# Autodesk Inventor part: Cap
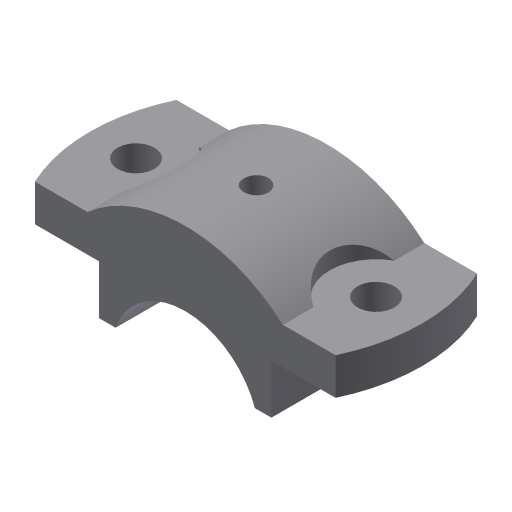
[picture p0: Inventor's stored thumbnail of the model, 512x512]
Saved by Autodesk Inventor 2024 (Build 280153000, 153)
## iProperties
Shininess: 77.0
Angle Display Precision: 2
Document Length Units: 11269
Document Angle Units: 11279
Document Time Units: 11290
Document Mass Units: 11283
Document Length Units Precision: 3
Document Angle Units Precision: 2
Created: 2002-02
Part Number: Cap
Document SubType Name: Modeling
Designer: ***
Density: 1 g/cm^3
Material: Generic
Appearance: Default
Density: 0.0
Volumn: 0.0
Area: 0.0
PropertySet Name: Model Information
Control State: 0
Master: False
Checked Out: False
Author: ***
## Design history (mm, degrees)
sketch "Sketch2"
  geometry: L1 (22.656, 22.99)-(28.029, 22.99); L2 (28.029, 22.99)-(28.029, 38.99); L3 (28.029, 38.99)-(54.029, 38.99); L4 (54.029, 38.99)-(54.029, 50.99); L5 (54.029, 50.99)-(31.778, 50.99); L6 (-22.599, 22.99)-(-27.971, 22.99); L7 (-27.971, 22.99)-(-27.971, 38.99); L8 (-27.971, 38.99)-(-53.971, 38.99); L9 (-53.971, 38.99)-(-53.971, 50.99); L10 (-53.971, 50.99)-(-31.72, 50.99); A1 r 24 centre (0.029, 14.99) between (22.656, 22.99) and (-22.599, 22.99); A2 r 48 centre (0.029, 14.99) between (31.778, 50.99) and (-31.72, 50.99)
  constraints: 20 end point, 5 equal length, 4 parallel, 4 perpendicular, 4 point on circle, 2 centre point, 1 coincident, 1 horizontal, 1 point on line
  dimensions: "d0" = 24 radius of A1; "d1" = 8 distance from line of L1 A1.centre; "d2" = 12 distance of L8.end L9.end; "d3" = 16 distance of L6.end L7.end; "d4" = 48 radius of A2; "d5" = 108 distance between parallel lines of L9 L4; "d6" = 56 distance between parallel lines of L7 L2
extrude "Extrusion1" new body sketch "Sketch2" stored distance "d7" = 46; taper "d8" = 0 deg
sketch "Sketch3"
  geometry: L1 (17.108, 0)-(40.349, 0); L2 (40.349, 0)-(40.349, -46); L3 (40.349, -46)-(17.108, -46); L4 (0, -46)-(22.251, -46) reference; L5 (22.251, 0)-(0, 0) reference; L6 (22.251, 0)-(22.251, -46) reference; A1 r 54 centre (-31.749, -23) between (17.108, -46) and (17.108, 0)
  constraints: 6 end point, 2 collinear, 2 point on circle, 1 centre point, 1 horizontal, 1 parallel, 1 perpendicular, 1 vertical alignment
  dimensions: "d9" = 54 radius of A1; "d10" = 54 distance from line of L6 A1.centre
extrude "Extrusion2" cut sketch "Sketch3" extent not by distance; stored distance "d11" = 46; taper "d12" = 0 deg
sketch "Sketch4"
  geometry: L1 (17.108, 46)-(0, 46) reference; A1 r 54 centre (-31.749, 23) between (17.108, 0) and (17.108, 46) reference; 1 further point
  dimensions: "d13" = 23 distance from line of L1 point (7.251, 23); "d14" = 39 distance of A1.centre point (7.251, 23)
hole "Hole1" sketch "Sketch4" diameter "d15" = 30; stored, may be unused: countersink angle "d19" = 82 deg, drill point angle "d21" = 118 deg; dims "d16" = 6, "d17" = 4, "d18" = 2, "d20" = 8
hole "Hole2" sketch "Sketch4" diameter "d22" = 12; stored, may be unused: countersink angle "d26" = 82 deg, drill point angle "d28" = 118 deg; dims "d23" = 6, "d24" = 4, "d25" = 2, "d27" = 8
workplane "Work Plane1"
mirror "Mirror1"
workplane "Work Plane2"
sketch "Sketch5"
  geometry: L1 (31.749, -23)-(-31.749, -23) reference; C1 r 6 at (39, 0) reference; 1 further point
  dimensions: "d30" = 23 distance from line of L1 point (0, 0); "d31" = 39 distance of C1.centre point (0, 0)
hole "Hole3" sketch "Sketch5" diameter "d32" = 6; stored, may be unused: countersink angle "d36" = 82 deg, drill point angle "d38" = 118 deg; dims "d33" = 6, "d34" = 8, "d35" = 16, "d37" = 8
body "Solid1"
other parameters: "d29" = -54
